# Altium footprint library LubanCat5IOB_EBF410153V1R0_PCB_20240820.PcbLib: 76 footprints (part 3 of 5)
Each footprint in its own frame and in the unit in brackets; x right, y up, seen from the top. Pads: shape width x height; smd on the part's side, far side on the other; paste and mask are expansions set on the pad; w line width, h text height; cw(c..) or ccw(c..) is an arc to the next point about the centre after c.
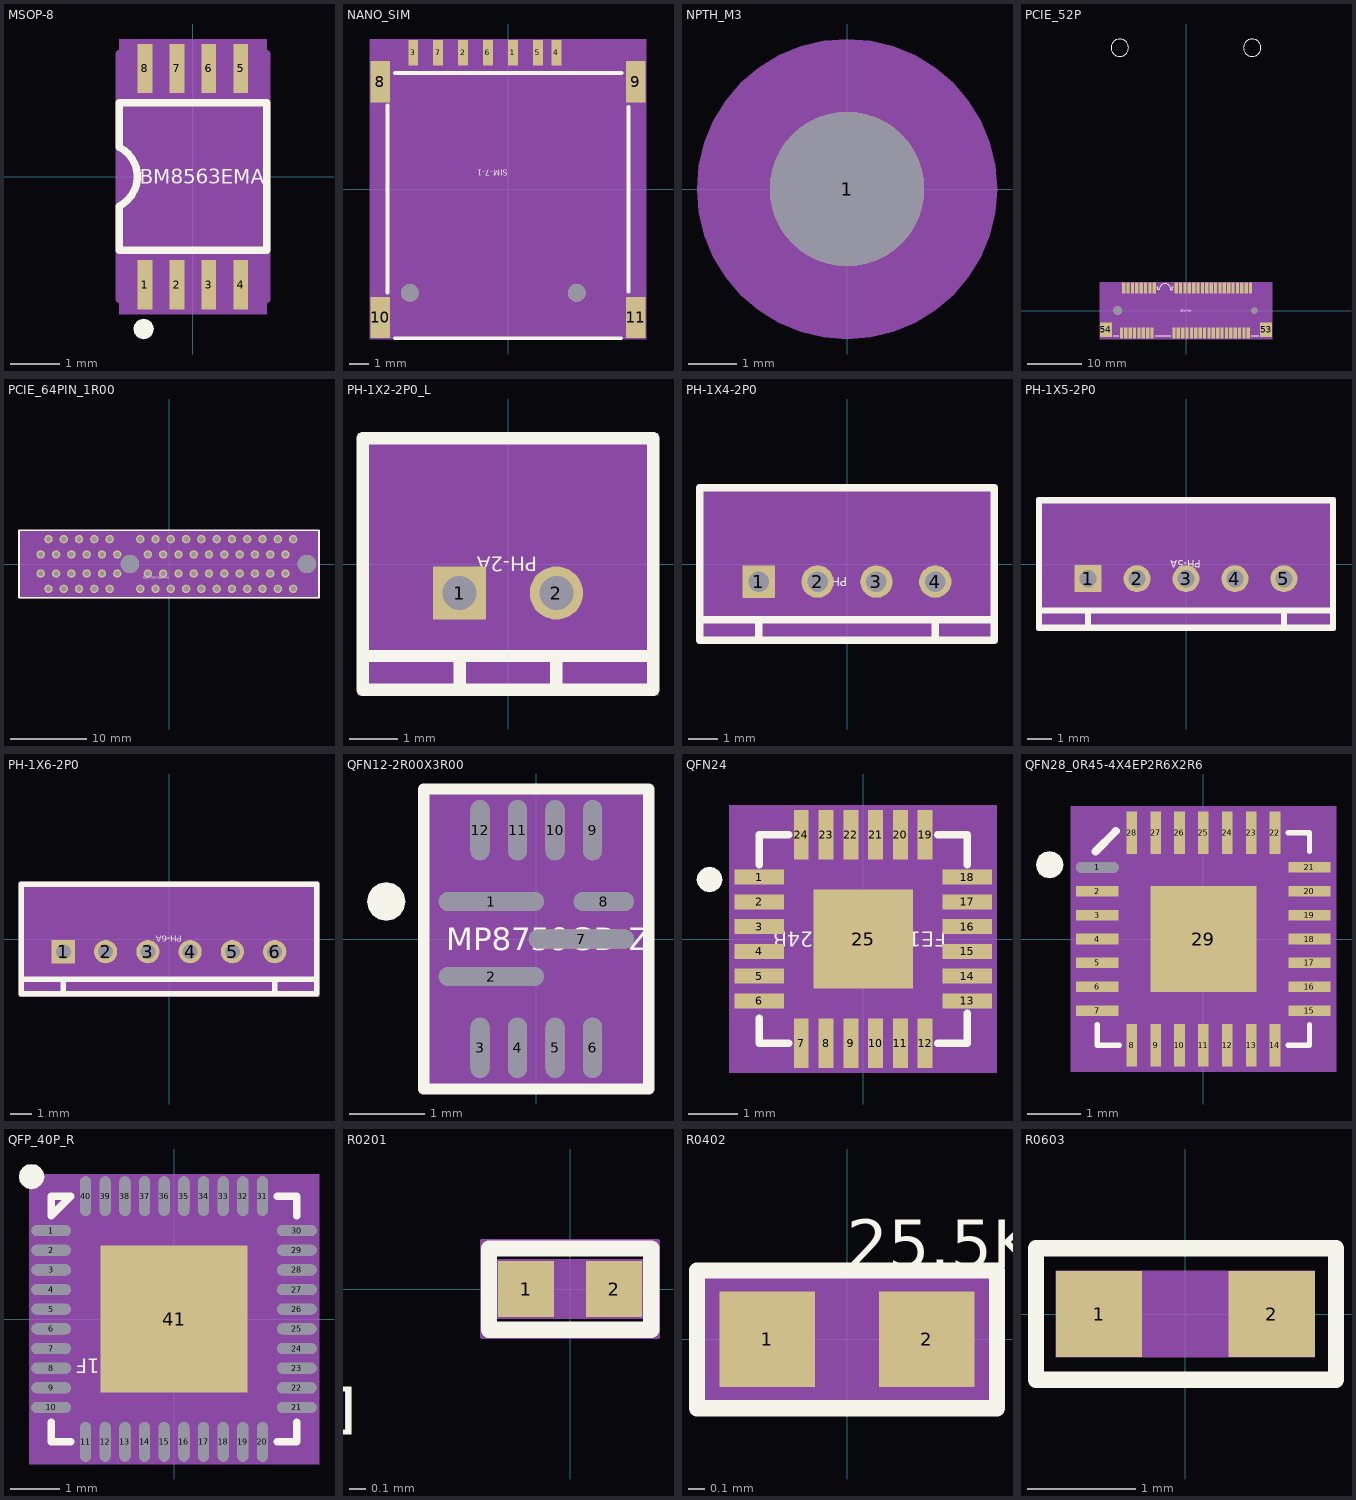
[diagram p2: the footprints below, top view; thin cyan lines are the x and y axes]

## MSOP-8 [mm] "MSOP-8"
pads (8):
  rect 0.3x1 smd: 1(-0.975,-2.2) 2(-0.325,-2.2) 3(0.325,-2.2) 4(0.975,-2.2) 5(0.975,2.2) 6(0.325,2.2) 7(-0.325,2.2) 8(-0.975,2.2)
Top Overlay:
  dashed: -0.796,-3.1 -0.812,-3.022 -0.856,-2.956 -0.922,-2.912 -1,-2.896 -1.078,-2.912 -1.1,-2.926 -1.144,-2.956 -1.188,-3.022 -1.204,-3.1 -1.188,-3.178 -1.144,-3.244 -1.1,-3.274 -1.078,-3.288 -1,-3.304 -0.922,-3.288 -0.856,-3.244 -0.812,-3.178
  lines w0.15: -1.5,-1.5 1.5,-1.5 1.5,1.5 -1.5,1.5 -1.5,0.6 cw(c-1.8,0) -1.5,-0.6 -1.5,-1.5
  text "BM8563EMA" at -1.08,-0.15 h0.3
Top 3D Body:
  region: -1.5,2.8 -1.5,-2.8 1.5,-2.8 1.5,2.8
Mechanical 15:
  text "4" at 0.861,-2.3 h0.3
  text "5" at 0.861,2.1 h0.3
  text "3" at 0.211,-2.3 h0.3
  text "2" at -0.439,-2.3 h0.3
  text "6" at 0.211,2.1 h0.3
  text "1" at -1.089,-2.3 h0.3
  text "8" at -1.089,2.1 h0.3
  text "7" at -0.439,2.1 h0.3
Top Assembly:
  lines w0.15: -1.5,-2.5 1.5,-2.5 1.5,2.5 -1.5,2.5 -1.5,-2.5 ; -1.5,-1.5 1.5,-1.5 1.5,1.5 -1.5,1.5 -1.5,-1.5
3D body: height 3.81, standoff 0, extent -1.5,-2.8 1.5,2.8

## NANO_SIM [mm] "NANO_SIM"
pads (13):
  rect 0.5x1.3 smd: 1(0.25,6.94) 2(-2.29,6.94) 3(-4.83,6.94) 4(2.47,6.94) 5(1.52,6.94) 6(-1.02,6.94) 7(-3.56,6.94)
  rect 1x2.1 smd: 8(-6.5,5.46) 9(6.5,5.46) 10(-6.5,-6.54) 11(6.5,-6.54)
  round 0.9 hole 0.9 unplated: ""(-5,-5.29) ""(3.5,-5.29)
Top Overlay:
  lines w0.2: -6.145,-5.268 -6.145,4.247 ; -5.756,5.9 5.784,5.9 ; -5.749,-7.6 0,-7.6 5.749,-7.6 ; 6.145,-5.215 6.145,4.189
  text "SIM-7-1" at 0,0.99 h0.3
Top 3D Body:
  region: -7.05,-7.64 -7.05,7.64 7.05,7.64 7.05,-7.64
Mechanical 15:
  text "11" at 6.5,-6.296 h0.3
  text "10" at -6.5,-6.296 h0.3
  text "5" at 1.52,7.062 h0.3
  text "9" at 6.5,5.582 h0.3
  text "8" at -6.5,5.582 h0.3
  text "3" at -4.83,7.062 h0.3
  text "1" at 0.25,7.062 h0.3
  text "7" at -3.56,7.062 h0.3
  text "2" at -2.29,7.062 h0.3
  text "6" at -1.02,7.062 h0.3
  text "4" at 2.47,7.062 h0.3
3D body: height 3.81, standoff 0, extent -7.05,-7.64 7.05,7.64

## NPTH_M3 [mm] "NPTH_M3"
pads (1):
  round 3.2 / inner round 1.524 / far side round 3.2 hole 3.2 unplated: 1(0,0)
Top Overlay:
  text "NPTH_M3" at -0.84,-0.15 h0.3
Top 3D Body:
  region: 3.11,0 3.071,0.486 2.957,0.961 2.771,1.412 2.516,1.828 2.199,2.199 1.828,2.516 1.412,2.771 0.961,2.957 0.486,3.071 0,3.11 -0.486,3.071 -0.961,2.957 -1.412,2.771 -1.551,2.686 -1.828,2.516 -2.199,2.199 -2.516,1.828 -2.771,1.412 -2.957,0.961 -3.071,0.486 -3.11,0 -3.071,-0.486 -2.957,-0.961 -2.771,-1.412 -2.516,-1.828 -2.199,-2.199 -1.828,-2.516 -1.551,-2.686 -1.412,-2.771 -0.961,-2.957 -0.486,-3.071 0,-3.11 0.486,-3.071 0.961,-2.957 1.412,-2.771 1.828,-2.516 2.199,-2.199 2.516,-1.828 2.771,-1.412 2.957,-0.961 3.071,-0.486
Mechanical 15:
  text "1" at -0.254,0 h0.64
3D body: height 3.81, standoff 0, extent -3.11,-3.11 3.11,3.11

## PCIE_52P [mm] "PCIE_52P"
pads (56):
  rect 0.6x2 smd: 1(-11.8,-4.1) 2(-11.4,4.1) 3(-11,-4.1) 4(-10.6,4.1) 5(-10.2,-4.1) 6(-9.8,4.1) 7(-9.4,-4.1) 8(-9,4.1) 9(-8.6,-4.1) 10(-8.2,4.1) 11(-7.8,-4.1) 12(-7.4,4.1) 13(-7,-4.1) 14(-6.6,4.1) 15(-6.2,-4.1) 16(-5.8,4.1) 17(-2.2,-4.1) 18(-1.8,4.1) 19(-1.4,-4.1) 20(-1,4.1) 21(-0.6,-4.1) 22(-0.2,4.1) 23(0.2,-4.1) 24(0.6,4.1) 25(1,-4.1) 26(1.4,4.1) 27(1.8,-4.1) 28(2.2,4.1) 29(2.6,-4.1) 30(3,4.1) 31(3.4,-4.1) 32(3.8,4.1) 33(4.2,-4.1) 34(4.6,4.1) 35(5,-4.1) 36(5.4,4.1) 37(5.8,-4.1) 38(6.2,4.1) 39(6.6,-4.1) 40(7,4.1) 41(7.4,-4.1) 42(7.8,4.1) 43(8.2,-4.1) 44(8.6,4.1) 45(9,-4.1) 46(9.4,4.1) 47(9.8,-4.1) 48(10.2,4.1) 49(10.6,-4.1) 50(11,4.1) 51(11.4,-4.1) 52(11.8,4.1)
  rect 2.15x2.6 smd: 53(14.65,-3.5) 54(-14.65,-3.5)
  round 1.6 hole 1.6 unplated: ""(-12.5,0)
  round 1.1 hole 1.1 unplated: ""(12.5,0)
Top Overlay:
  circle w0.2: c12.1,48.049 r1.6
  circle w0.2: c-12.1,48.049 r1.6
  lines w0.2: -13.3,-4.6 -12.3,-4.6 ; -5.6,-4.6 -2.8,-4.6 ; -5.325,4.387 -5.165,4.387 -5.165,3.883 -4.887,3.883 cw(c-3.843,3.859) -2.8,3.859 -2.8,3.847 -2.474,3.847 -2.474,4.381 -2.29,4.381 ; 11.9,-4.6 13.3,-4.6
  text "MINI-PCIE" at 1.08,0.15 h0.3
Top 3D Body:
  region: -15.8,-5.2 -15.8,5.2 15.8,5.2 15.8,-5.2
Mechanical 15:
  text "25" at 1.488,-4.1 h0.3
  text "18" at -1.312,4.1 h0.3
  text "21" at -0.112,-4.1 h0.3
  text "50" at 11.488,4.1 h0.3
  text "37" at 6.288,-4.1 h0.3
  text "43" at 8.688,-4.1 h0.3
  text "35" at 5.488,-4.1 h0.3
  text "29" at 3.088,-4.1 h0.3
  text "27" at 2.288,-4.1 h0.3
  text "15" at -5.712,-4.1 h0.3
  text "40" at 7.488,4.1 h0.3
  text "34" at 5.088,4.1 h0.3
  text "26" at 1.888,4.1 h0.3
  text "54" at -14.162,-3.5 h0.3
  text "53" at 15.138,-3.5 h0.3
  text "4" at -10.356,4.1 h0.3
  text "9" at -8.356,-4.1 h0.3
  text "13" at -6.512,-4.1 h0.3
  text "23" at 0.688,-4.1 h0.3
  text "22" at 0.288,4.1 h0.3
  text "10" at -7.712,4.1 h0.3
  text "7" at -9.156,-4.1 h0.3
  text "33" at 4.688,-4.1 h0.3
  text "31" at 3.888,-4.1 h0.3
  text "38" at 6.688,4.1 h0.3
  text "8" at -8.756,4.1 h0.3
  text "11" at -7.312,-4.1 h0.3
  text "1" at -11.556,-4.1 h0.3
  text "14" at -6.112,4.1 h0.3
  text "39" at 7.088,-4.1 h0.3
  text "41" at 7.888,-4.1 h0.3
  text "52" at 12.288,4.1 h0.3
  text "2" at -11.156,4.1 h0.3
  text "24" at 1.088,4.1 h0.3
  text "12" at -6.912,4.1 h0.3
  text "36" at 5.888,4.1 h0.3
  text "20" at -0.512,4.1 h0.3
  text "32" at 4.288,4.1 h0.3
  text "19" at -0.912,-4.1 h0.3
  text "44" at 9.088,4.1 h0.3
  text "46" at 9.888,4.1 h0.3
  text "30" at 3.488,4.1 h0.3
  text "28" at 2.688,4.1 h0.3
  text "5" at -9.956,-4.1 h0.3
  text "16" at -5.312,4.1 h0.3
  text "17" at -1.712,-4.1 h0.3
  text "51" at 11.888,-4.1 h0.3
  text "49" at 11.088,-4.1 h0.3
  text "47" at 10.288,-4.1 h0.3
  text "45" at 9.488,-4.1 h0.3
  text "48" at 10.688,4.1 h0.3
  text "6" at -9.556,4.1 h0.3
  text "3" at -10.756,-4.1 h0.3
  text "42" at 8.288,4.1 h0.3
Top Assembly:
  dashed: -15.8,5.2 -15.8,-5.2 15.8,-5.2 15.8,5.2
3D body: height 3.81, standoff 0, extent -15.8,-5.2 15.8,5.2

## PCIE_64PIN_1R00 [mm] "PCIE_64PIN_1R00"
pads (66):
  round 1.1 hole 0.7: A1(-16.765,1.25) A4(-13.765,3.25) A12(-3.765,3.25) A15(-0.765,1.25) A18(2.235,3.25) A20(4.235,3.25) A23(7.235,1.25) A24(8.235,3.25) A27(11.235,1.25) A28(12.235,3.25) A31(15.235,1.25) B4(-13.765,-3.25) B7(-10.765,-1.25) B13(-2.765,-1.25) B16(0.235,-3.25) B18(2.235,-3.25) B21(5.235,-1.25) B22(6.235,-3.25) B25(9.235,-1.25) B26(10.235,-3.25) B29(13.235,-1.25) B32(16.235,-3.25)
  round 1.1 / inner round 1.524 / far side round 1.1 hole 0.7: A2(-15.765,3.25) A3(-14.765,1.25) A5(-12.765,1.25) A6(-11.765,3.25) A7(-10.765,1.25) A8(-9.765,3.25) A9(-8.765,1.25) A10(-7.765,3.25) A11(-6.765,1.25) A13(-2.765,1.25) A14(-1.765,3.25) A16(0.235,3.25) A17(1.235,1.25) A19(3.235,1.25) A21(5.235,1.25) A22(6.235,3.25) A25(9.235,1.25) A26(10.235,3.25) A29(13.235,1.25) A30(14.235,3.25) A32(16.235,3.25) B1(-16.765,-1.25) B2(-15.765,-3.25) B3(-14.765,-1.25) B5(-12.765,-1.25) B6(-11.765,-3.25) B8(-9.765,-3.25) B9(-8.765,-1.25) B10(-7.765,-3.25) B11(-6.765,-1.25) B12(-3.765,-3.25) B14(-1.765,-3.25) B15(-0.765,-1.25) B17(1.235,-1.25) B19(3.235,-1.25) B20(4.235,-3.25) B23(7.235,-1.25) B24(8.235,-3.25) B27(11.235,-1.25) B28(12.235,-3.25) B30(14.235,-3.25) B31(15.235,-1.25)
  round 2.4 hole 2.4 unplated: ""(-5.115,0) ""(18.035,0)
Top Overlay:
  lines w0.2: -19.615,-4.39 19.615,-4.39 19.615,4.39 -19.615,4.39 -19.615,-4.39
  text "AAA-PCI-161-K03" at 0,-1.65 h0.3
Top 3D Body:
  region: -19.615,-4.39 -19.615,4.39 19.615,4.39 19.615,-4.39
Mechanical 15:
  text "B12" at -2.985,-5.174 h0.64
  text "A11" at -5.985,-0.674 h0.64
  text "B11" at -5.985,-3.174 h0.64
  text "B10" at -6.985,-5.174 h0.64
  text "B8" at -9.285,-4.666 h0.64
  text "A9" at -8.285,-0.166 h0.64
  text "A10" at -6.985,1.326 h0.64
  text "B2" at -15.285,-4.666 h0.64
  text "A3" at -14.285,-0.166 h0.64
  text "B1" at -16.285,-2.666 h0.64
  text "B3" at -14.285,-2.666 h0.64
  text "A2" at -15.285,1.834 h0.64
  text "A12" at -2.985,1.326 h0.64
  text "B13" at -1.985,-3.174 h0.64
  text "B4" at -13.285,-4.666 h0.64
  text "A18" at 3.015,1.326 h0.64
  text "A20" at 5.015,1.326 h0.64
  text "A24" at 9.015,1.326 h0.64
  text "A28" at 13.015,1.326 h0.64
  text "A15" at 0.015,-0.674 h0.64
  text "A23" at 8.015,-0.674 h0.64
  text "A27" at 12.015,-0.674 h0.64
  text "A31" at 16.015,-0.674 h0.64
  text "B21" at 6.015,-3.174 h0.64
  text "B25" at 10.015,-3.174 h0.64
  text "B29" at 14.015,-3.174 h0.64
  text "B16" at 1.015,-5.174 h0.64
  text "B18" at 3.015,-5.174 h0.64
  text "B22" at 7.015,-5.174 h0.64
  text "B26" at 11.015,-5.174 h0.64
  text "B32" at 17.015,-5.174 h0.64
  text "B7" at -10.285,-2.666 h0.64
  text "A1" at -16.285,-0.166 h0.64
  text "A4" at -13.285,1.834 h0.64
  text "A22" at 7.015,1.326 h0.64
  text "A21" at 6.015,-0.674 h0.64
  text "A17" at 2.015,-0.674 h0.64
  text "A16" at 1.015,1.326 h0.64
  text "A14" at -0.985,1.326 h0.64
  text "A13" at -1.985,-0.674 h0.64
  text "B20" at 5.015,-5.174 h0.64
  text "B19" at 4.015,-3.174 h0.64
  text "B31" at 16.015,-3.174 h0.64
  text "B17" at 2.015,-3.174 h0.64
  text "B15" at 0.015,-3.174 h0.64
  text "B14" at -0.985,-5.174 h0.64
  text "B6" at -11.285,-4.666 h0.64
  text "B5" at -12.285,-2.666 h0.64
  text "B30" at 15.015,-5.174 h0.64
  text "A32" at 17.015,1.326 h0.64
  text "A19" at 4.015,-0.674 h0.64
  text "B27" at 12.015,-3.174 h0.64
  text "B23" at 8.015,-3.174 h0.64
  text "B28" at 13.015,-5.174 h0.64
  text "B24" at 9.015,-5.174 h0.64
  text "A29" at 14.015,-0.674 h0.64
  text "A25" at 10.015,-0.674 h0.64
  text "A30" at 15.015,1.326 h0.64
  text "A26" at 11.015,1.326 h0.64
  text "B9" at -8.285,-2.666 h0.64
  text "A8" at -9.285,1.834 h0.64
  text "A7" at -10.285,-0.166 h0.64
  text "A6" at -11.285,1.834 h0.64
  text "A5" at -12.285,-0.166 h0.64
Top Assembly:
  lines w0.025: -19.615,-4.39 -19.615,4.39 19.615,4.39 19.615,-4.39 -19.615,-4.39
3D body: height 3.81, standoff 0, extent -19.615,-4.39 19.615,4.39

## PH-1X2-2P0_L [mm] "PH-1X2-2P0_L"
pads (2):
  rect 1.1x1.1 / inner round 1.524 / far side rect 1.1x1.1 hole 0.7: 1(-1,-0.6)
  round 1.1 / inner round 1.524 / far side round 1.1 hole 0.7: 2(1,-0.6)
Top Overlay:
  lines w0.254: -3,-1.9 3,-1.9 ; -1,-2.6 -1,-1.9 ; 1,-2.6 1,-1.9 ; -3,-2.6 -3,2.6 3,2.6 3,-2.6 -3,-2.6
  text "PH-2A" at 0.6,0.15 h0.3
Bottom Overlay:
  lines w0.6: 0,-1.1 0,-0.1
Top 3D Body:
  region: -3.1,2.7 -3.1,-2.7 3.1,-2.7 3.1,2.7
Mechanical 15:
  text "2" at 1.254,-0.6 h0.64
  text "1" at -0.746,-0.6 h0.64
Top Assembly:
  lines w0.025: -3.1,-2.7 -3.1,2.7 3.1,2.7 3.1,-2.7 -3.1,-2.7
3D body: height 3.81, standoff 0, extent -3.1,-2.7 3.1,2.7

## PH-1X4-2P0 [mm] "PH-1X4-2P0"
pads (4):
  rect 1.1x1.1 / inner round 1.524 / far side rect 1.1x1.1 hole 0.7: 1(-3,-0.6)
  round 1.1 / inner round 1.524 / far side round 1.1 hole 0.7: 2(-1,-0.6) 3(1,-0.6)
  round 1.1 hole 0.7: 4(3,-0.6)
Top Overlay:
  lines w0.254: -5,-1.9 5,-1.9 ; -3,-2.6 -3,-1.9 ; 3,-2.6 3,-1.9 ; -5,-2.6 -5,2.6 5,2.6 5,-2.6 -5,-2.6
  text "PH-4A" at 0,-0.45 h0.3
Bottom Overlay:
  lines w0.5: -2,-1.5 -2,0.3 ; 0,-1.5 0,0.3 ; 2,-1.5 2,0.3 ; -3.9,-1.5 -3.9,0.3 3.9,0.3 3.9,-1.5 -3.6,-1.5 -3.9,-1.5
Top 3D Body:
  region: -5.1,2.7 -5.1,-2.7 5.1,-2.7 5.1,2.7
Mechanical 15:
  text "4" at 3,-0.976 h0.94
  text "3" at 1,-0.976 h0.94
  text "2" at -1,-0.976 h0.94
  text "1" at -3,-0.976 h0.94
3D body: height 3.81, standoff 0, extent -5.1,-2.7 5.1,2.7

## PH-1X5-2P0 [mm] "PH-1X5-2P0"
pads (5):
  rect 1.1x1.1 / inner round 1.524 / far side rect 1.1x1.1 hole 0.7: 1(-4,-0.6)
  round 1.1 / inner round 1.524 / far side round 1.1 hole 0.7: 2(-2,-0.6) 3(0,-0.6) 4(2,-0.6)
  round 1.1 hole 0.7: 5(4,-0.6)
Top Overlay:
  lines w0.254: -6,-1.9 6,-1.9 ; -4,-2.6 -4,-1.9 ; 4,-2.6 4,-1.9 ; 5.988,2.6 -6,2.6 -6,-2.6 6,-2.6 6,2.6
  text "PH-5A" at 0.6,0.15 h0.3
Bottom Overlay:
  lines w0.5: -3,-1.1 -3,-0.1 ; -1,-1.1 -1,-0.1 ; 1,-1.1 1,-0.1 ; 3,-1.1 3,-0.1
Top 3D Body:
  region: -6.127,-2.727 6.127,-2.727 6.127,2.727 -6.127,2.727
Mechanical 15:
  text "5" at 4.122,-0.6 h0.3
  text "2" at -1.878,-0.6 h0.3
  text "3" at 0.122,-0.6 h0.3
  text "4" at 2.122,-0.6 h0.3
  text "1" at -3.878,-0.6 h0.3
3D body: height 3.81, standoff 0, extent -6.127,-2.727 6.127,2.727

## PH-1X6-2P0 [mm] "PH-1X6-2P0"
pads (6):
  rect 1.1x1.1 / inner round 1.524 / far side rect 1.1x1.1 hole 0.7: 1(-5,-0.6)
  round 1.1 hole 0.7: 2(-3,-0.6) 4(1,-0.6) 6(5,-0.6)
  round 1.1 / inner round 1.524 / far side round 1.1 hole 0.7: 3(-1,-0.6) 5(3,-0.6)
Top Overlay:
  lines w0.254: -7,-1.9 7,-1.9 ; -5,-2.6 -5,-1.9 ; 5,-2.6 5,-1.9 ; -7,-2.6 7,-2.6 7,2.6 -7,2.6 -7,-2.6
  text "PH-6A" at 0.6,0.15 h0.3
Bottom Overlay:
  lines w0.5: -4,-1.1 -4,-0.1 ; -2,-1.1 -2,-0.1 ; 0,-1.1 0,-0.1 ; 2,-1.1 2,-0.1 ; 4,-1.1 4,-0.1
Top 3D Body:
  region: -7.1,2.7 -7.1,-2.7 7.1,-2.7 7.1,2.7
Mechanical 15:
  text "1" at -4.746,-0.6 h0.64
  text "2" at -2.746,-0.6 h0.64
  text "4" at 1.254,-0.6 h0.64
  text "6" at 5.254,-0.6 h0.64
  text "5" at 3.254,-0.6 h0.64
  text "3" at -0.746,-0.6 h0.64
Top Assembly:
  lines w0.025: -7.1,-2.7 -7.1,2.7 7.1,2.7 7.1,-2.7 -7.1,-2.7
3D body: height 3.81, standoff 0, extent -7.1,-2.7 7.1,2.7

## QFN12-2R00X3R00 [mm] "QFN12-2R00X3R00"
pads (12):
  oval 1.4x0.25 smd: 1(-0.6,0.5) 2(-0.6,-0.5) 7(0.6,0)
  oval 0.25x0.8 smd: 3(-0.75,-1.45) 4(-0.25,-1.45) 5(0.25,-1.45) 6(0.75,-1.45) 9(0.75,1.45) 10(0.25,1.45) 11(-0.25,1.45) 12(-0.75,1.45)
  oval 0.8x0.25 smd: 8(0.9,0.5)
Top Overlay:
  dashed: -1.745,0.5 -1.765,0.598 -1.82,0.68 -1.902,0.735 -2,0.755 -2.098,0.735 -2.125,0.717 -2.18,0.68 -2.235,0.598 -2.255,0.5 -2.235,0.402 -2.18,0.32 -2.125,0.283 -2.098,0.265 -2,0.245 -1.902,0.265 -1.82,0.32 -1.765,0.402
  lines w0.15: -1.5,-2 1.5,-2 1.5,2 1,2 -1.5,2 -1.5,-2
  text "MP8759GD-Z" at -1.2,-0.15 h0.3
Top 3D Body:
  region: -1.5,2 -1.5,-2 1.5,-2 1.5,2
Mechanical 15:
  text "9" at 0.71,1.45 h0.1
  text "6" at 0.71,-1.45 h0.1
  text "1" at -0.64,0.5 h0.1
  text "12" at -0.83,1.45 h0.1
  text "10" at 0.17,1.45 h0.1
  text "2" at -0.64,-0.5 h0.1
  text "11" at -0.33,1.45 h0.1
  text "3" at -0.79,-1.45 h0.1
  text "8" at 0.86,0.5 h0.1
  text "7" at 0.56,0 h0.1
  text "5" at 0.21,-1.45 h0.1
  text "4" at -0.29,-1.45 h0.1
Top Assembly:
  lines w0.15: -1,-1.5 1,-1.5 1,1.5 -1,1.5 -1,-1.5
3D body: height 3.81, standoff 0, extent -1.5,-2 1.5,2

## QFN24 [mm] "QFN24"
pads (25):
  rect 1x0.3 smd: 1(-2.1,1.25) 2(-2.1,0.75) 3(-2.1,0.25) 4(-2.1,-0.25) 5(-2.1,-0.75) 6(-2.1,-1.25) 13(2.1,-1.25) 14(2.1,-0.75) 15(2.1,-0.25) 16(2.1,0.25) 17(2.1,0.75) 18(2.1,1.25)
  rect 0.3x1 smd: 7(-1.25,-2.1) 8(-0.75,-2.1) 9(-0.25,-2.1) 10(0.25,-2.1) 11(0.75,-2.1) 12(1.25,-2.1) 19(1.25,2.1) 20(0.75,2.1) 21(0.25,2.1) 22(-0.25,2.1) 23(-0.75,2.1) 24(-1.25,2.1)
  rect 2x2 smd: 25(0,0)
Top Overlay:
  dashed: -3.355,1.2 -3.335,1.102 -3.28,1.02 -3.198,0.965 -3.1,0.945 -3.002,0.965 -2.975,0.983 -2.92,1.02 -2.865,1.102 -2.845,1.2 -2.865,1.298 -2.92,1.38 -2.975,1.417 -3.002,1.435 -3.1,1.455 -3.198,1.435 -3.28,1.38 -3.335,1.298
  lines w0.15: -2.1,-1.6 -2.1,-2.1 -1.5,-2.1 ; -2.1,1.5 -2.1,2.1 -1.5,2.1 ; 1.5,-2.1 2.1,-2.1 2.1,-1.5 ; 1.5,2.1 2.1,2.1 2.1,1.5
  text "FE1.1s-BQFN24B" at 1.68,0.15 h0.3
Top 3D Body:
  region: -2.7,-2.7 2.7,-2.7 2.7,2.7 -2.7,2.7
Mechanical 15:
  text "15" at 2.405,-0.25 h0.38
  text "11" at 1.055,-2.1 h0.38
  text "25" at 0.305,0 h0.38
  text "16" at 2.405,0.25 h0.38
  text "12" at 1.555,-2.1 h0.38
  text "14" at 2.405,-0.75 h0.38
  text "6" at -1.948,-1.25 h0.38
  text "7" at -1.098,-2.1 h0.38
  text "8" at -0.598,-2.1 h0.38
  text "3" at -1.948,0.25 h0.38
  text "18" at 2.405,1.25 h0.38
  text "20" at 1.055,2.1 h0.38
  text "1" at -1.948,1.25 h0.38
  text "5" at -1.948,-0.75 h0.38
  text "10" at 0.555,-2.1 h0.38
  text "13" at 2.405,-1.25 h0.38
  text "9" at -0.098,-2.1 h0.38
  text "17" at 2.405,0.75 h0.38
  text "4" at -1.948,-0.25 h0.38
  text "19" at 1.555,2.1 h0.38
  text "2" at -1.948,0.75 h0.38
  text "24" at -0.945,2.1 h0.38
  text "23" at -0.445,2.1 h0.38
  text "22" at 0.055,2.1 h0.38
  text "21" at 0.555,2.1 h0.38
Top Assembly:
  lines w0.2: -2.05,-2.05 -2.05,2.05 2.05,2.05 2.05,-2.05 -2.05,-2.05
3D body: height 3.81, standoff 0, extent -2.7,-2.7 2.7,2.7

## QFN28_0R45-4X4EP2R6X2R6 [mm] "QFN28_0R45-4X4EP2R6X2R6"
pads (29):
  oval 0.8x0.2 smd: 1(-2,1.35)
  rect 0.8x0.2 smd: 2(-2,0.9) 3(-2,0.45) 4(-2,0) 5(-2,-0.45) 6(-2,-0.9) 7(-2,-1.35) 15(2,-1.35) 16(2,-0.9) 17(2,-0.45) 18(2,0) 19(2,0.45) 20(2,0.9) 21(2,1.35)
  rect 0.2x0.8 smd: 8(-1.35,-2) 9(-0.9,-2) 10(-0.45,-2) 11(0,-2) 12(0.45,-2) 13(0.9,-2) 14(1.35,-2) 22(1.35,2) 23(0.9,2) 24(0.45,2) 25(0,2) 26(-0.45,2) 27(-0.9,2) 28(-1.35,2)
  rect 2x2 smd: 29(0,0)
Top Overlay:
  dashed: -2.645,1.4 -2.664,1.498 -2.72,1.58 -2.802,1.636 -2.9,1.655 -2.998,1.636 -3.025,1.617 -3.08,1.58 -3.136,1.498 -3.155,1.4 -3.136,1.302 -3.08,1.22 -3.025,1.183 -2.998,1.164 -2.9,1.145 -2.802,1.164 -2.72,1.22 -2.664,1.302
  lines w0.1: -2,-1.615 -2,-2 -1.587,-2 ; 1.6,-2 2,-2 2,-1.615 ; 1.6,2 2,2 2,1.657
  lines w0.152: -2.032,1.651 -1.651,2.032
  text "ES8388" at -0.72,-0.15 h0.3
Top 3D Body:
  region: -2.5,2.5 -2.5,-2.5 2.5,-2.5 2.5,2.5
Mechanical 15:
  text "14" at 1.27,-2 h0.1
  text "15" at 1.92,-1.35 h0.1
  text "18" at 1.92,0 h0.1
  text "13" at 0.82,-2 h0.1
  text "4" at -2.04,0 h0.1
  text "29" at -0.08,0 h0.1
  text "26" at -0.53,2 h0.1
  text "10" at -0.53,-2 h0.1
  text "22" at 1.27,2 h0.1
  text "5" at -2.04,-0.45 h0.1
  text "28" at -1.43,2 h0.1
  text "24" at 0.37,2 h0.1
  text "23" at 0.82,2 h0.1
  text "8" at -1.39,-2 h0.1
  text "6" at -2.04,-0.9 h0.1
  text "20" at 1.92,0.9 h0.1
  text "7" at -2.04,-1.35 h0.1
  text "27" at -0.98,2 h0.1
  text "11" at -0.08,-2 h0.1
  text "1" at -2.04,1.35 h0.1
  text "16" at 1.92,-0.9 h0.1
  text "17" at 1.92,-0.45 h0.1
  text "19" at 1.92,0.45 h0.1
  text "21" at 1.92,1.35 h0.1
  text "2" at -2.04,0.9 h0.1
  text "3" at -2.04,0.45 h0.1
  text "12" at 0.37,-2 h0.1
  text "25" at -0.08,2 h0.1
  text "9" at -0.94,-2 h0.1
Top Assembly:
  lines w0.15: -2,-2 2,-2 2,2 -2,2 -2,-2
3D body: height 3.81, standoff 0, extent -2.5,-2.5 2.5,2.5

## QFP_40P_R [mil] "QFP_40P_R"
pads (41):
  oval 31.5x8.66 smd: 1(-98.43,70.87) 2(-98.43,55.12) 3(-98.43,39.37) 4(-98.43,23.62) 5(-98.43,7.87) 6(-98.43,-7.87) 7(-98.43,-23.62) 8(-98.43,-39.37) 9(-98.43,-55.12) 10(-98.43,-70.87) 21(98.43,-70.87) 22(98.43,-55.12) 23(98.43,-39.37) 24(98.43,-23.62) 25(98.43,-7.87) 26(98.43,7.87) 27(98.43,23.62) 28(98.43,39.37) 29(98.43,55.12) 30(98.43,70.87)
  oval 8.66x31.5 smd: 11(-70.87,-98.43) 12(-55.12,-98.43) 13(-39.37,-98.43) 14(-23.62,-98.43) 15(-7.87,-98.43) 16(7.87,-98.43) 17(23.62,-98.43) 18(39.37,-98.43) 19(55.12,-98.43) 20(70.87,-98.43) 31(70.87,98.43) 32(55.12,98.43) 33(39.37,98.43) 34(23.62,98.43) 35(7.87,98.43) 36(-7.87,98.43) 37(-23.62,98.43) 38(-39.37,98.43) 39(-55.12,98.43) 40(-70.87,98.43)
  rect 118.11x118.11 smd: 41(0,0)
Top Overlay:
  dashed: -114.17,124.21 -118.01,123.44 -121.27,121.27 -123.44,118.01 -124.21,114.17 -123.44,110.33 -122.71,109.24 -121.27,107.08 -118.01,104.9 -114.17,104.14 -110.33,104.9 -107.08,107.08 -105.63,109.24 -104.9,110.33 -104.14,114.17 -104.9,118.01 -107.08,121.27 -110.33,123.44
  lines w5.91: -98.43,-82.68 -98.43,-98.43 -82.68,-98.43 ; 82.68,-98.43 98.43,-98.43 98.43,-82.68 ; 82.68,98.43 98.43,98.43 98.43,82.68 ; -98.43,82.68 -98.43,98.43 -82.68,98.43 -98.43,82.68
  text "RTL8211F" at 0.01,-31.89 h11.81
Top 3D Body:
  region: -116.14,-116.14 116.14,-116.14 116.14,116.14 -116.14,116.14
Mechanical 15:
  text "37" at -18.7,91.54 h9.84
  text "36" at -2.95,91.54 h9.84
  text "28" at 98.43,25.59 h9.84
  text "41" at 0,-26 h20
  text "24" at 98.43,-37.4 h9.84
  text "12" at -50.2,-105.32 h9.84
  text "13" at -34.45,-105.32 h9.84
  text "25" at 98.43,-21.65 h9.84
  text "18" at 44.29,-105.32 h9.84
  text "14" at -18.7,-105.32 h9.84
  text "33" at 44.29,91.54 h9.84
  text "35" at 12.79,91.54 h9.84
  text "32" at 60.04,91.54 h9.84
  text "30" at 98.43,57.09 h9.84
  text "20" at 75.79,-105.32 h9.84
  text "23" at 98.43,-53.15 h9.84
  text "27" at 98.43,9.84 h9.84
  text "26" at 98.43,-5.91 h9.84
  text "22" at 98.43,-68.9 h9.84
  text "16" at 12.79,-105.32 h9.84
  text "19" at 60.04,-105.32 h9.84
  text "39" at -50.2,91.54 h9.84
  text "34" at 28.54,91.54 h9.84
  text "21" at 98.43,-84.65 h9.84
  text "8" at -98.43,-47.24 h9.84
  text "3" at -98.43,31.5 h9.84
  text "38" at -34.45,91.54 h9.84
  text "31" at 75.79,91.54 h9.84
  text "17" at 28.54,-105.32 h9.84
  text "15" at -2.95,-105.32 h9.84
  text "11" at -65.95,-105.32 h9.84
  text "40" at -65.95,91.54 h9.84
  text "29" at 98.43,41.34 h9.84
  text "10" at -98.43,-82.68 h9.84
  text "9" at -98.43,-62.99 h9.84
  text "7" at -98.43,-31.49 h9.84
  text "6" at -98.43,-15.74 h9.84
  text "5" at -98.43,0 h9.84
  text "4" at -98.43,15.75 h9.84
  text "2" at -98.43,47.25 h9.84
  text "1" at -98.43,63 h9.84
Top Assembly:
  lines w1: -98.43,-98.43 -98.43,98.43 98.43,98.43 98.43,-98.43 -98.43,-98.43
3D body: height 150, standoff 0, extent -116.14,-116.14 116.14,116.14

## R0201 [mm] "R0201"
pads (2):
  rect 0.35x0.35 smd: 1(-0.275,0) 2(0.275,0)
Top Overlay:
  lines w0.102: -0.508,-0.254 0.508,-0.254 0.508,0.254 -0.508,0.254 -0.508,-0.254
  text ".Designator" at -0.36,0.15 h0.3
  text "D1250-5R5C" at -1.327,-0.612 h0.3
Top 3D Body:
  region: -0.475,-0.175 -0.475,0.175 0.475,0.175 0.475,-0.175
Mechanical 15:
  text "1" at -0.59,0 h0.79
  text "2" at -0.04,0 h0.79
Top Assembly:
  lines w0.025: -0.55,-0.3 -0.55,0.3 0.55,0.3 0.55,-0.3 -0.55,-0.3 ; -0.475,-0.175 -0.475,0.175 0.475,0.175 0.475,-0.175 -0.475,-0.175
  text "D1250-5R5C" at 0,0 h0.79
3D body: height 3.81, standoff 0, extent -0.475,-0.175 0.475,0.175

## R0402 [mm] "R0402"
pads (2):
  rect 0.599x0.599 smd: 1(-0.5,0) 2(0.5,0)
Top Overlay:
  lines w0.102: -0.94,-0.432 0.94,-0.432 0.94,0.432 -0.94,0.432 -0.94,-0.432
  text "25.5K" at 0,0.45 h0.3
Top 3D Body:
  region: 0.94,0.432 0.94,-0.432 -0.94,-0.432 -0.94,0.432
Mechanical 15:
  text "2" at 0.5,0.254 h0.64
  text "1" at -0.5,0.254 h0.64
Top Assembly:
  dashed: -0.94,-0.432 -0.94,0.432 0.94,0.432 0.94,-0.432
3D body: height 3.81, standoff 0, extent -0.94,-0.432 0.94,0.432

## R0603 [mil] "R0603"
pads (2):
  rect 31.5x31.5 smd: 1(-31.5,0) 2(31.5,0)
Top Overlay:
  lines w6: -54.5,-24 55,-24 55,24 -54.5,24 -54.5,-24
  text "10K" at -14.17,5.91 h11.81
Top 3D Body:
  region: -47.24,-15.75 -47.24,15.75 47.24,15.75 47.24,-15.75
Mechanical 15:
  text "2" at 13.5,0 h45
  text "1" at -49.5,0 h45
3D body: height 150, standoff 0, extent -47.24,-15.75 47.24,15.75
